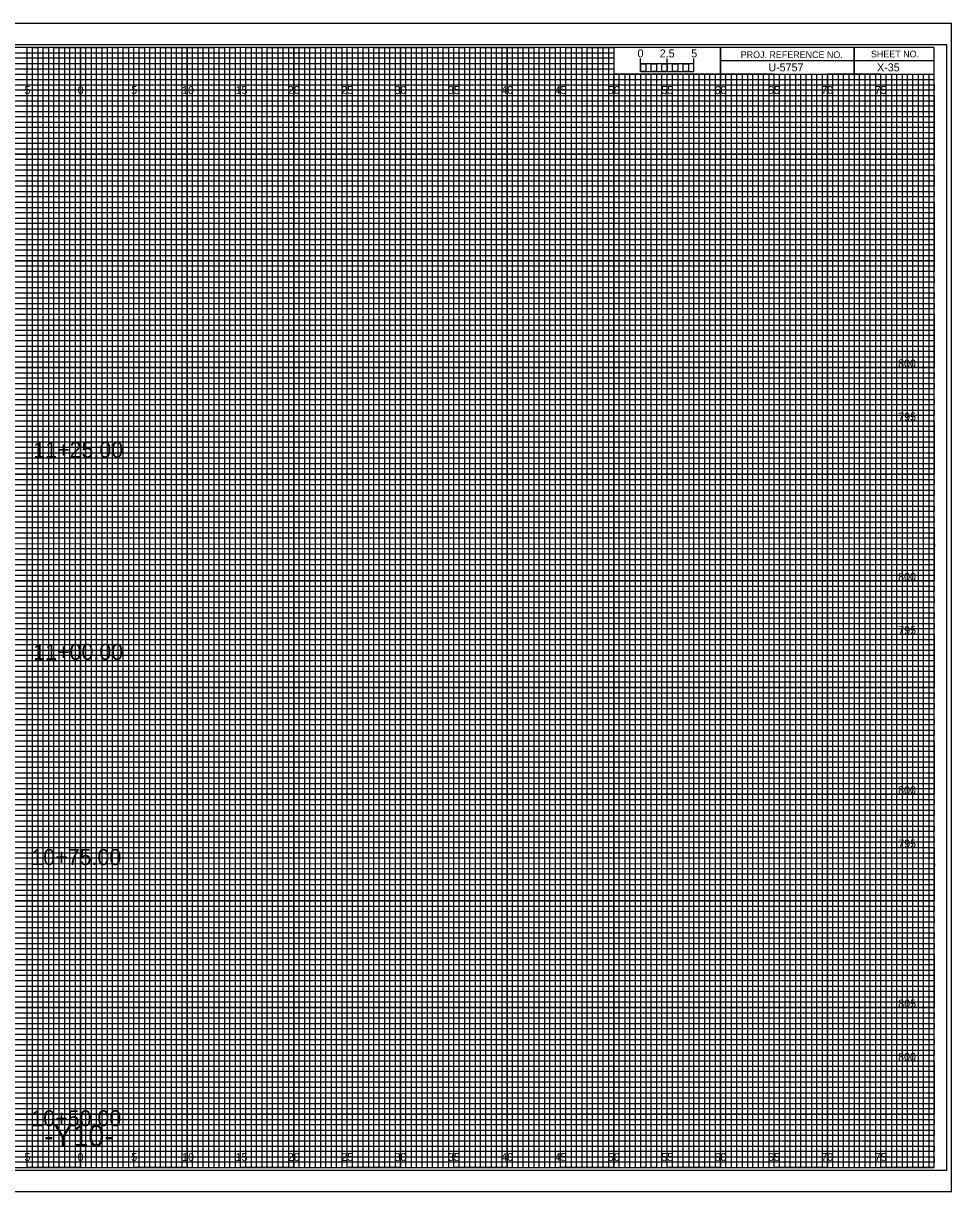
# Model space of a CAD drawing. Extents: x -7 to 162, y -2 to 107.
# Drawn here: x 74.6 to 161.7, y -2.3 to 107.3 of the extents above; entities that cross this region are included whole.
import ezdxf

# ---------------------------------------------------------------- set-up
doc = ezdxf.new("R2010")
doc.units = 0
for name, color, linetype in [('Exist Cross Section Cell', 7, 'Continuous'), ('Exist XS Center Line Elevation Label', 7, 'Continuous'), ('Prop CMT Pvmt Course 2 Wedge', 7, 'Continuous'), ('Prop XS Alignment Label', 7, 'Continuous'), ('Prop XS Bar Scale Labels', 7, 'Continuous'), ('Prop XS Elevation Labels', 7, 'Continuous'), ('Prop XS Hydro Elevations', 7, 'Continuous'), ('Prop XS Project Number', 7, 'Continuous'), ('Prop XS SE Text', 7, 'Continuous'), ('Prop XS Sheet Number', 7, 'Continuous'), ('Prop XS Side Slope Text', 7, 'Continuous'), ('Prop XS Station Labels', 7, 'Continuous'), ('Sheet Cross Section Scale CELL', 7, 'Continuous'), ('Sheet Cutting Line CELL', 7, 'Continuous'), ('Sheet DOT Grid CELL', 7, 'Continuous'), ('Sheet Plot Border Inside CELL', 7, 'Continuous'), ('Sheet Plot Border Outside CELL', 7, 'Continuous')]:
    doc.layers.add(name, color=color, linetype=linetype)

msp = doc.modelspace()

# ---------------------------------------------------------------- linework, layer by layer
at = {"layer": 'Exist Cross Section Cell'}
for p, q in [((75, 105), (70, 105)), ((75, 0), (75, 105)), ((85, 105), (80, 105)), ((80, 105), (80, 0)), ((85, 0), (85, 105)), ((95, 105), (90, 105)), ((90, 105), (90, 0)), ((95, 0), (95, 105)), ((105, 105), (100, 105)), ((100, 105), (100, 0)), ((105, 0), (105, 105)), ((115, 105), (110, 105)), ((110, 105), (110, 0)), ((115, 0), (115, 105)), ((125, 105), (120, 105)), ((120, 105), (120, 0)), ((125, 0), (125, 105)), ((130, 105), (130, 0)), ((135, 0), (135, 102.5)), ((145, 102.5), (140, 102.5)), ((140, 102.5), (140, 0)), ((145, 0), (145, 102.5)), ((155, 102.5), (150, 102.5)), ((150, 102.5), (150, 0)), ((155, 0), (155, 102.5)), ((80, 0), (75, 0)), ((90, 0), (85, 0)), ((100, 0), (95, 0)), ((110, 0), (105, 0)), ((120, 0), (115, 0)), ((130, 0), (125, 0)), ((140, 0), (135, 0)), ((150, 0), (145, 0)), ((160, 0), (155, 0)), ((160, 0), (160, 0))]:
    msp.add_line(p, q, dxfattribs=at)
for points in [[(0, 100), (160, 100), (160, 95), (0, 95)], [(0, 90), (160, 90), (160, 85), (0, 85)], [(0, 80), (160, 80), (160, 75), (0, 75)], [(0, 70), (160, 70), (160, 65), (0, 65)], [(0, 60), (160, 60), (160, 55), (0, 55)], [(0, 50), (160, 50), (160, 45), (0, 45)], [(0, 40), (160, 40), (160, 35), (0, 35)], [(0, 30), (160, 30), (160, 25), (0, 25)], [(0, 20), (160, 20), (160, 15), (0, 15)], [(0, 10), (160, 10), (160, 5), (0, 5)]]:
    msp.add_lwpolyline(points, dxfattribs=at)
at = {"layer": 'Exist XS Center Line Elevation Label'}
for points in [[(72.5, 0), (77.5, 0), (77.5, 105), (82.5, 105), (82.5, 0), (87.5, 0), (87.5, 105), (92.5, 105), (92.5, 0), (97.5, 0), (97.5, 105), (102.5, 105), (102.5, 0), (107.5, 0), (107.5, 105), (112.5, 105), (112.5, 0), (117.5, 0), (117.5, 105), (122.5, 105), (122.5, 0), (127.5, 0), (127.5, 105), (129.97, 105), (130, 105), (130, 102.5), (132.5, 102.5), (132.5, 0), (137.5, 0), (137.5, 102.5), (142.5, 102.5), (142.5, 0), (147.5, 0), (147.5, 102.5), (152.5, 102.5), (152.5, 0), (157.5, 0), (157.5, 102.5)], [(0, 102.5), (137.5, 102.5)], [(0, 92.5), (160, 92.5), (160, 97.5), (0, 97.5)], [(0, 82.5), (160, 82.5), (160, 87.5), (0, 87.5)], [(0, 72.5), (160, 72.5), (160, 77.5), (0, 77.5)], [(0, 62.5), (160, 62.5), (160, 67.5), (0, 67.5)], [(0, 52.5), (160, 52.5), (160, 57.5), (0, 57.5)], [(0, 42.5), (160, 42.5), (160, 47.5), (0, 47.5)], [(0, 32.5), (160, 32.5), (160, 37.5), (0, 37.5)], [(0, 22.5), (160, 22.5), (160, 27.5), (0, 27.5)], [(0, 12.5), (160, 12.5), (160, 17.5), (0, 17.5)], [(0, 2.5), (160, 2.5), (160, 7.5), (0, 7.5)]]:
    msp.add_lwpolyline(points, dxfattribs=at)
at = {"layer": 'Prop CMT Pvmt Course 2 Wedge'}
for p, q in [((133.5, 102.5), (133, 102.5)), ((133, 102.5), (133, 0)), ((133.5, 0), (133.5, 102.5)), ((134.5, 102.5), (134, 102.5)), ((134, 102.5), (134, 0)), ((134.5, 0), (134.5, 102.5)), ((133, 0), (132.5, 0)), ((134, 0), (133.5, 0))]:
    msp.add_line(p, q, dxfattribs=at)
for points in [[(75, 0), (75.5, 0), (75.5, 105), (76, 105), (76, 0)], [(76, 0), (76.5, 0), (76.5, 105), (77, 105), (77, 0)], [(77.5, 0), (78, 0), (78, 105), (78.5, 105), (78.5, 0)], [(78.5, 0), (79, 0), (79, 105), (79.5, 105), (79.5, 0)], [(80, 0), (80.5, 0), (80.5, 105), (81, 105), (81, 0)], [(81, 0), (81.5, 0), (81.5, 105), (82, 105), (82, 0)], [(82.5, 0), (83, 0), (83, 105), (83.5, 105), (83.5, 0)], [(83.5, 0), (84, 0), (84, 105), (84.5, 105), (84.5, 0)], [(85, 0), (85.5, 0), (85.5, 105), (86, 105), (86, 0)], [(86, 0), (86.5, 0), (86.5, 105), (87, 105), (87, 0)], [(87.5, 0), (88, 0), (88, 105), (88.5, 105), (88.5, 0)], [(88.5, 0), (89, 0), (89, 105), (89.5, 105), (89.5, 0)], [(90, 0), (90.5, 0), (90.5, 105), (91, 105), (91, 0)], [(91, 0), (91.5, 0), (91.5, 105), (92, 105), (92, 0)], [(92.5, 0), (93, 0), (93, 105), (93.5, 105), (93.5, 0)], [(93.5, 0), (94, 0), (94, 105), (94.5, 105), (94.5, 0)], [(95, 0), (95.5, 0), (95.5, 105), (96, 105), (96, 0)], [(96, 0), (96.5, 0), (96.5, 105), (97, 105), (97, 0)], [(97.5, 0), (98, 0), (98, 105), (98.5, 105), (98.5, 0)], [(98.5, 0), (99, 0), (99, 105), (99.5, 105), (99.5, 0)], [(100, 0), (100.5, 0), (100.5, 105), (101, 105), (101, 0)], [(101, 0), (101.5, 0), (101.5, 105), (102, 105), (102, 0)], [(102.5, 0), (103, 0), (103, 105), (103.5, 105), (103.5, 0)], [(103.5, 0), (104, 0), (104, 105), (104.5, 105), (104.5, 0)], [(105, 0), (105.5, 0), (105.5, 105), (106, 105), (106, 0)], [(106, 0), (106.5, 0), (106.5, 105), (107, 105), (107, 0)], [(107.5, 0), (108, 0), (108, 105), (108.5, 105), (108.5, 0)], [(108.5, 0), (109, 0), (109, 105), (109.5, 105), (109.5, 0)], [(110, 0), (110.5, 0), (110.5, 105), (111, 105), (111, 0)], [(111, 0), (111.5, 0), (111.5, 105), (112, 105), (112, 0)], [(112.5, 0), (113, 0), (113, 105), (113.5, 105), (113.5, 0)], [(113.5, 0), (114, 0), (114, 105), (114.5, 105), (114.5, 0)], [(115, 0), (115.5, 0), (115.5, 105), (116, 105), (116, 0)], [(116, 0), (116.5, 0), (116.5, 105), (117, 105), (117, 0)], [(117.5, 0), (118, 0), (118, 105), (118.5, 105), (118.5, 0)], [(118.5, 0), (119, 0), (119, 105), (119.5, 105), (119.5, 0)], [(120, 0), (120.5, 0), (120.5, 105), (121, 105), (121, 0)], [(121, 0), (121.5, 0), (121.5, 105), (122, 105), (122, 0)], [(122.5, 0), (123, 0), (123, 105), (123.5, 105), (123.5, 0)], [(123.5, 0), (124, 0), (124, 105), (124.5, 105), (124.5, 0)], [(125, 0), (125.5, 0), (125.5, 105), (126, 105), (126, 0)], [(126, 0), (126.5, 0), (126.5, 105), (127, 105), (127, 0)], [(127.5, 0), (128, 0), (128, 105), (128.5, 105), (128.5, 0)], [(128.5, 0), (129, 0), (129, 105), (129.5, 105), (129.5, 0)], [(130, 0), (130.5, 0), (130.5, 102.5), (131.01, 102.5), (131.01, 0)], [(131, 0), (131.5, 0), (131.5, 102.5), (132, 102.5), (132, 0)], [(135, 0), (135.49, 0), (135.49, 102.5), (136, 102.5), (136, 0)], [(136, 0), (136.5, 0), (136.5, 102.5), (137.03, 102.5), (137.03, 0)], [(137.5, 0), (138, 0), (138, 102.5), (138.5, 102.5), (138.5, 0)], [(138.5, 0), (139, 0), (139, 102.5), (139.5, 102.5), (139.5, 0)], [(140, 0), (140.5, 0), (140.5, 102.5), (141, 102.5), (141, 0)], [(141, 0), (141.5, 0), (141.5, 102.5), (142, 102.5), (142, 0)], [(142.5, 0), (143, 0), (143, 102.5), (143.5, 102.5), (143.5, 0)], [(143.5, 0), (144, 0), (144, 102.5), (144.5, 102.5), (144.5, 0)], [(145, 0), (145.5, 0), (145.5, 102.5), (146, 102.5), (146, 0)], [(146, 0), (146.5, 0), (146.5, 102.5), (147, 102.5), (147, 0)], [(147.5, 0), (148, 0), (148, 102.5), (148.5, 102.5), (148.5, 0)], [(148.5, 0), (149, 0), (149, 102.5), (149.5, 102.5), (149.5, 0)], [(150, 0), (150.5, 0), (150.5, 102.5), (151, 102.5), (151, 0)], [(151, 0), (151.5, 0), (151.5, 102.5), (152, 102.5), (152, 0)], [(152.5, 0), (153, 0), (153, 102.5), (153.5, 102.5), (153.5, 0)], [(153.5, 0), (154, 0), (154, 102.5), (154.5, 102.5), (154.5, 0)], [(155, 0), (155.5, 0), (155.5, 102.5), (156, 102.5), (156, 0)], [(156, 0), (156.5, 0), (156.5, 102.5), (157, 102.5), (157, 0)], [(157.5, 0), (158, 0), (158, 102.5), (158.5, 102.5), (158.5, 0)], [(158.5, 0), (159, 0), (159, 102.5), (159.5, 102.5), (159.5, 0)]]:
    msp.add_lwpolyline(points, dxfattribs=at)
at = {"layer": 'Prop XS Hydro Elevations'}
for p, q in [((152.5, 105), (152.5, 102.5)), ((152.5, 102.5), (152.5, 105)), ((160, 103.75), (140, 103.75)), ((140, 103.75), (140, 102.5)), ((140, 102.5), (160, 102.5))]:
    msp.add_line(p, q, dxfattribs=at)
for points in [[(160, 105), (0, 105), (0, 0), (160, 0)], [(140, 105), (130, 105), (130, 102.52), (140, 102.52)], [(160, 105), (140, 105), (140, 102.5), (160, 102.5)]]:
    msp.add_lwpolyline(points, close=True, dxfattribs=at)
at = {"layer": 'Prop XS Side Slope Text'}
for p, q in [((0, 104.5), (130, 104.5)), ((130, 104.5), (130, 103.99)), ((130, 103.99), (0, 103.99)), ((0, 103.5), (130, 103.5)), ((130, 102.95), (0, 102.95)), ((130, 103.5), (130, 102.95)), ((0, 102), (160, 102))]:
    msp.add_line(p, q, dxfattribs=at)
for points in [[(0, 101.5), (135, 101.5), (160, 101.5), (160, 101), (0, 101)], [(0, 100.5), (160, 100.5), (160, 99.5), (0, 99.5)], [(0, 99), (160, 99), (160, 98.5), (0, 98.49)], [(0, 98), (160, 98), (160, 97), (0, 97)], [(0, 96.5), (160, 96.5), (160, 96), (0, 96)], [(0, 95.5), (160, 95.5), (160, 94.5), (0, 94.5)], [(0, 94), (160, 94), (160, 93.5), (0, 93.5)], [(0, 93), (160, 93), (160, 92), (0, 92)], [(0, 91.5), (160, 91.5), (160, 91), (0, 91)], [(0, 90.5), (160, 90.5), (160, 89.5), (0, 89.5)], [(0, 89), (160, 89), (160, 88.5), (0, 88.5)], [(0, 88), (160, 88), (160, 86.98), (160, 86.5), (160, 86), (0, 86)], [(0, 87), (160, 87), (160, 86.5), (0, 86.5)], [(0, 85.5), (160, 85.5), (160, 84.5), (0, 84.52)], [(0, 84.52), (160, 84.5), (160, 84), (0, 84)], [(0, 83.5), (160, 83.5), (160, 83), (0, 83)], [(0, 82), (160, 82), (160, 81.5), (0, 81.5)], [(0, 81), (160, 81), (160, 80.5), (0, 80.5)], [(-0.04, 79.45), (160, 79.45), (160, 78.94), (-0.04, 78.94)], [(0, 78.5), (160, 78.5), (160, 78), (0, 78)], [(0, 77), (160, 77), (160, 76.5), (0, 76.5)], [(0, 76), (160, 76), (160, 75.5), (0, 75.5)], [(0, 74.5), (160, 74.5), (160, 74), (0, 74)], [(0, 73.5), (160, 73.5), (160, 73), (0, 73)], [(0, 72), (160, 72), (160, 71.5), (0, 71.5)], [(0, 71), (160, 71), (160, 70.5), (0, 70.5)], [(0, 69.5), (160, 69.5), (160, 68.99), (0, 69)], [(0, 68.5), (160, 68.5), (160, 68), (0, 68)], [(0, 67), (160, 67), (160, 66.5), (0, 66.5)], [(0, 66), (160, 66), (160, 65.5), (0, 65.5)], [(0, 64.5), (160, 64.5), (160, 64), (0, 64)], [(0, 63.5), (160, 63.5), (160, 63), (0, 63)], [(0, 62), (160, 62), (160, 61.5), (0, 61.5)], [(0, 61), (160, 61), (160, 60.5), (0, 60.5)], [(0, 59.5), (160, 59.5), (160, 59), (0, 59)], [(0, 58.5), (160.03, 58.45), (160, 58), (0, 58)], [(0, 57), (160, 57), (160, 56.5), (0, 56.5)], [(0, 56), (160, 56), (160, 55.5), (0, 55.5)], [(0, 54.5), (160, 54.5), (160, 54), (0, 54)], [(0, 53.5), (160, 53.5), (160, 53), (0, 53)], [(0, 52), (160, 52), (160, 51.5), (0, 51.5)], [(0, 51), (160, 51), (160, 50.5), (0, 50.5)], [(0, 49.5), (160, 49.5), (160, 49), (0, 49)], [(0, 48.5), (160, 48.5), (160, 48), (0, 48)], [(0, 47), (160, 47), (160, 46.5), (0, 46.5)], [(0, 46), (160, 46), (160, 45.5), (0, 45.5)], [(0, 44.5), (160, 44.5), (160, 44), (0, 44)], [(0, 43.5), (160, 43.5), (160, 43), (0, 43)], [(0, 42), (160, 42), (160, 41.5), (0, 41.5)], [(0, 41), (160, 41), (160, 40.5), (0, 40.5)], [(0, 39.5), (160, 39.5), (160, 38.99), (0, 39)], [(0, 38.5), (160, 38.5), (160, 38), (0, 38)], [(0, 37), (160, 37), (160, 36.5), (0, 36.5)], [(0, 36), (160, 36), (160, 35.5), (0, 35.5)], [(0, 34.5), (160, 34.5), (160, 34), (0, 34)], [(0, 33.5), (160, 33.5), (160, 33), (0, 33)], [(0, 32), (160, 32), (160, 31.5), (0, 31.5)], [(0, 31), (160, 31), (160, 30.5), (0, 30.5)], [(0, 29.5), (160, 29.5), (160, 29), (0, 29)], [(0, 28.5), (160.03, 28.46), (160, 28), (0, 28)], [(0, 27), (160, 27), (160, 26.5), (0, 26.5)], [(0, 26), (160, 26), (160, 25.5), (0, 25.5)], [(0, 24.5), (160, 24.5), (160, 24), (0, 24)], [(0, 23.5), (160, 23.5), (160, 23), (0, 23)], [(0, 22), (160, 22), (160, 21.5), (0, 21.5)], [(0, 21), (160, 21), (160, 20.5), (0, 20.5)], [(0, 19.5), (160, 19.5), (160, 19), (0, 19)], [(0, 18.5), (160, 18.5), (160, 18), (0, 18)], [(0, 17), (160, 17), (160, 16.5), (0, 16.5)], [(0, 16), (160, 16), (160, 15.5), (0, 15.5)], [(0, 14.5), (160, 14.5), (160, 14), (0, 14)], [(0, 13.5), (160, 13.5), (160, 13), (0, 13)], [(0, 12), (160, 12), (160, 11.5), (0, 11.5)], [(0, 11), (160, 11), (160, 10.5), (0, 10.5)], [(0, 9.5), (160, 9.5), (160, 9), (0, 9)], [(0, 8.5), (160, 8.5), (160, 8), (0, 8)], [(0, 7), (160, 7), (160, 6.5), (0, 6.5)], [(0, 6), (160, 6), (160, 5.5), (0, 5.5)], [(0, 4.5), (160, 4.5), (160, 4), (0, 4)], [(0, 3.5), (160, 3.5), (160, 3), (0, 3)], [(0, 2), (160, 2), (160, 1.5), (0, 1.5)], [(0, 1), (160, 1), (160, 0.5), (0, 0.5)]]:
    msp.add_lwpolyline(points, dxfattribs=at)
at = {"layer": 'Sheet Cross Section Scale CELL'}
for p, q in [((132.5, 102.75), (132.5, 103.95)), ((132.5, 103.45), (132.5, 103.95)), ((135, 102.75), (135, 103.95)), ((137.5, 102.75), (137.5, 103.95)), ((137.5, 103.45), (137.5, 103.95))]:
    msp.add_line(p, q, dxfattribs=at)
for points in [[(137.5, 103.45), (132.5, 103.45), (132.5, 102.75), (137.5, 102.75)], [(132.5, 103.45), (133, 103.45), (133, 102.75), (132.5, 102.75)], [(133.5, 103.45), (134, 103.45), (134, 102.75), (133.5, 102.75)], [(134.5, 103.45), (135, 103.45), (135, 102.75), (134.5, 102.75)], [(135.5, 103.45), (136, 103.45), (136, 102.75), (135.5, 102.75)], [(136.5, 103.45), (137, 103.45), (137, 102.75), (136.5, 102.75)]]:
    msp.add_lwpolyline(points, close=True, dxfattribs=at)
at = {"layer": 'Sheet Cutting Line CELL'}
for p, q in [((161.65, 107.25), (-6.7, 107.25)), ((-6.7, -2.25), (161.65, -2.25))]:
    msp.add_line(p, q, dxfattribs=at)
at = {"layer": 'Sheet DOT Grid CELL'}
for p, q in [((75, 0), (75, 105)), ((80, 0), (80, 105)), ((85, 0), (85, 105)), ((90, 0), (90, 105)), ((95, 0), (95, 105)), ((100, 0), (100, 105)), ((105, 0), (105, 105)), ((110, 0), (110, 105)), ((115, 0), (115, 105)), ((120, 0), (120, 105)), ((125, 0), (125, 105)), ((130, 0), (130, 102.34)), ((135, 0), (135, 102.34)), ((140, 0), (140, 102.34)), ((145, 0), (145, 102.34)), ((150, 0), (150, 102.34)), ((155, 0), (155, 102.34)), ((0, 100), (160, 100)), ((0, 95), (160, 95)), ((0, 90), (160, 90)), ((0, 85), (160, 85)), ((0, 80), (160, 80)), ((0, 75), (160, 75)), ((0, 70), (160, 70)), ((0, 65), (160, 65)), ((0, 60), (160, 60)), ((0, 55), (160, 55)), ((0, 50), (160, 50)), ((0, 45), (160, 45)), ((0, 40), (160, 40)), ((0, 35), (160, 35)), ((0, 30), (160, 30)), ((0, 25), (160, 25)), ((0, 20), (160, 20)), ((0, 15), (160, 15)), ((0, 10), (160, 10)), ((0, 5), (160, 5))]:
    msp.add_line(p, q, dxfattribs=at)
at = {"layer": 'Sheet Plot Border Inside CELL'}
msp.add_lwpolyline([(-5.4, -0.25), (161.2, -0.25), (161.2, 105.25), (-5.4, 105.25)], close=True, dxfattribs=at)
at = {"layer": 'Sheet Plot Border Outside CELL'}
msp.add_lwpolyline([(-6.7, -2.25), (161.65, -2.25), (161.65, 107.25), (-6.7, 107.25)], close=True, dxfattribs=at)

# ---------------------------------------------------------------- texts
at = {"layer": 'Prop XS Alignment Label'}
msp.add_text('-Y10-', height=2, dxfattribs=at).set_placement((76.57, 2))
at = {"layer": 'Prop XS Bar Scale Labels'}
for s, p in [('2.5', (134.29, 104.06)), ('5', (137.24, 104.06))]:
    msp.add_text(s, height=0.75, dxfattribs=at).set_placement(p)
at = {"layer": 'Prop XS Elevation Labels'}
for s, p in [('800', (156.63, 75)), ('795', (156.64, 70)), ('800', (156.63, 55)), ('795', (156.64, 50)), ('800', (156.63, 35)), ('795', (156.64, 30)), ('805', (156.64, 15)), ('800', (156.63, 10))]:
    msp.add_text(s, height=0.75, dxfattribs=at).set_placement(p)
at = {"layer": 'Prop XS Hydro Elevations'}
for s, p in [('PROJ. REFERENCE NO.', (141.88, 104)), ('SHEET NO.', (154.09, 104.06))]:
    msp.add_text(s, height=0.625, dxfattribs=at).set_placement(p)
at = {"layer": 'Prop XS Project Number'}
msp.add_text('U-5757', height=0.75, dxfattribs=at).set_placement((144.47, 102.75))
at = {"layer": 'Prop XS SE Text'}
for s, p in [('5', (74.74, 100.62)), ('0', (79.73, 100.62)), ('0', (79.73, 100.62)), ('5', (84.74, 100.62)), ('10', (89.52, 100.62)), ('15', (94.53, 100.62)), ('20', (99.43, 100.62)), ('25', (104.44, 100.62)), ('30', (109.43, 100.62)), ('35', (114.44, 100.62)), ('40', (119.43, 100.62)), ('45', (124.44, 100.62)), ('50', (129.43, 100.62)), ('55', (134.44, 100.62)), ('60', (139.43, 100.62)), ('65', (144.44, 100.62)), ('70', (149.43, 100.62)), ('75', (154.44, 100.62)), ('5', (74.74, 0.62)), ('0', (79.73, 0.62)), ('0', (79.73, 0.62)), ('5', (84.74, 0.62)), ('10', (89.52, 0.62)), ('15', (94.53, 0.62)), ('20', (99.43, 0.62)), ('25', (104.44, 0.62)), ('30', (109.43, 0.62)), ('35', (114.44, 0.62)), ('40', (119.43, 0.62)), ('45', (124.44, 0.62)), ('50', (129.43, 0.62)), ('55', (134.44, 0.62)), ('60', (139.43, 0.62)), ('65', (144.44, 0.62)), ('70', (149.43, 0.62)), ('75', (154.44, 0.62))]:
    msp.add_text(s, height=0.75, dxfattribs=at).set_placement(p)
at = {"layer": 'Prop XS Sheet Number'}
msp.add_text('X-35', height=0.75, dxfattribs=at).set_placement((154.66, 102.75))
at = {"layer": 'Prop XS Station Labels'}
for s, p in [('11+25.00', (75.57, 66.54)), ('11+00.00', (75.57, 47.59)), ('10+75.00', (75.39, 28.36)), ('10+50.00', (75.39, 3.88))]:
    msp.add_text(s, height=1.5, dxfattribs=at).set_placement(p)
at = {"layer": 'Sheet Cross Section Scale CELL'}
msp.add_text('0', height=0.75, dxfattribs=at).set_placement((132.21, 104.06))

doc.saveas('drawing.dxf')
